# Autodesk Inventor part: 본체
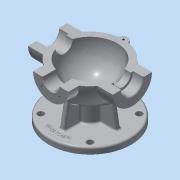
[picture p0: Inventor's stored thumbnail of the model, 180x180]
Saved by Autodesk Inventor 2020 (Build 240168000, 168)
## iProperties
Created: 2015-12
Part Number: 본체
Material: 알루미늄 6061
Document SubType Name: Modeling
Designer: mduedu
Density: 2.71 g/cm^3
Mass: 966.367 g
Surface Area: 788.536 cm^2
Volume: 356.593 cm^3
Appearance: 알루미늄 - 평지
Author: mduedu
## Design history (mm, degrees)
sketch "스케치1"
  geometry: L1 (-53, 0)-(53, 0); A1 r 53 centre (0, 0) between (53, 0) and (-53, 0); 2 further points
  constraints: 2 coincident, 2 end point, 2 point on circle, 1 centre point, 1 horizontal, 1 midpoint
  dimensions: "d0" = 53 radius of A1
revolve "회전1" sketch "스케치1" stored, may be unused: angle "d2" = 90 deg
feature "쉘1" dims "d11" = 10
node "작업 평면1"
sketch "스케치2"
  geometry: C1 r 31 at (0, 0); 1 further point
  constraints: 1 centre point, 1 coincident
  dimensions: "d4" = 62 diameter of C1
extrude "돌출1" join sketch "스케치2" stored distance "d5" = 10; taper "d6" = 0 deg
node "작업 평면2"
sketch "스케치3"
  geometry: C1 r 28 at (0, 0); 1 further point
  constraints: 1 centre point, 1 coincident
  dimensions: "d8" = 56 diameter of C1
extrude "돌출2" join sketch "스케치3" stored distance "d9" = 10; taper "d10" = 0 deg
hole "구멍1" diameter "d14" = 35; stored, may be unused: countersink angle "d18" = 90 deg, drill point angle "d20" = 0 deg; dims "d12" = 10, "d13" = 10, "d15" = 6, "d16" = 4, "d17" = 2, "d19" = 16
hole "구멍2" diameter "d23" = 27; stored, may be unused: countersink angle "d27" = 90 deg, drill point angle "d29" = 0 deg; dims "d21" = 10, "d22" = 10, "d24" = 6, "d25" = 4, "d26" = 2, "d28" = 16
fillet "모깎기1" dims "d30" = 0.3
hole "구멍3" diameter "d33" = 26; stored, may be unused: countersink angle "d37" = 90 deg, drill point angle "d39" = 0 deg; dims "d31" = 10, "d32" = 10, "d34" = 6, "d35" = 4, "d36" = 2, "d38" = 16
chamfer "모따기1" distance "d40" = 1; stored, may be unused: second distance "d41" = 2, angle "d42" = 45 deg
sketch "스케치4"
  geometry: L1 (0, 0)-(0, -25); L2 (0, 0)-(-17.678, -17.678); A1 r 25 centre (0, 0) between (-17.678, -17.678) and (0, -25); 1 further point
  constraints: 4 end point, 2 point on circle, 1 centre point, 1 coincident, 1 vertical
  dimensions: "d43" = 50 diameter of A1; "d47" = 45 deg angle of L1 L2
hole "구멍4" sketch "스케치4" at (-17.678, -17.678) diameter "d49" = 3.242; stored, may be unused: countersink angle "d53" = 90 deg, drill point angle "d55" = 118 deg; dims "d50" = 11, "d51" = 4, "d52" = 2, "d54" = 13
sketch "스케치5"
  geometry: L1 (0, 0)-(0, -20); L2 (0, 0)-(-14.142, -14.142); A1 r 20 centre (0, 0) between (0, -20) and (-14.142, -14.142); 2 further points
  constraints: 4 end point, 2 coincident, 2 point on circle, 1 centre point, 1 vertical
  dimensions: "d59" = 40 diameter of A1; "d65" = 45 deg angle of L1 L2
hole "구멍5" sketch "스케치5" at (-14.142, -14.142) diameter "d67" = 3.242; stored, may be unused: countersink angle "d71" = 90 deg, drill point angle "d73" = 118 deg; dims "d68" = 8, "d69" = 4, "d70" = 2, "d72" = 10
node "작업 평면3"
sketch "스케치6"
  geometry: C1 r 65 at (0, 0); 1 further point
  constraints: 1 centre point, 1 coincident
  dimensions: "d78" = 130 diameter of C1
extrude "돌출3" join sketch "스케치6" distance "d80" = 10; taper "d81" = 0 deg
sketch "스케치7"
  geometry: C1 r 20 at (0, 0); 1 further point
  constraints: 1 centre point, 1 coincident
  dimensions: "d82" = 40 diameter of C1
extrude "돌출4" join sketch "스케치7" stored distance "d84" = 10; taper "d85" = 0 deg
sketch "스케치8"
  geometry: 2 further points
  constraints: 1 coincident
hole "구멍6" sketch "스케치8" at (0, 0) diameter "d86" = 20; stored, may be unused: countersink angle "d90" = 90 deg, drill point angle "d92" = 118 deg; dims "d87" = 7, "d88" = 40, "d89" = 5, "d91" = 10
fillet "모깎기2" dims "d93" = 0.3
sketch "스케치9"
  geometry: L1 (65, -75)-(-65, -75) reference; L2 (-45, -75)-(-38.245, -36.692); A1 r 53 centre (0, 0) between (42.988, 31) and (42.988, -31) reference; 1 further point
  constraints: 2 end point, 1 point on circle, 1 point on line
  dimensions: "d94" = 45 horizontal distance of L2.start point (0, 0); "d95" = 80 deg angle of L2 L1
feature "리브1" sketch "스케치9" dims "d96" = 1, "d97" = 8, "d98" = 0, "d99" = 0, "d100" = 1, "d101" = 1
sketch "스케치10"
  geometry: L1 (0, 0)-(0, -55); L2 (0, 0)-(-38.891, -38.891); A1 r 55 centre (0, 0) between (0, -55) and (-38.891, -38.891); 2 further points
  constraints: 4 end point, 2 coincident, 2 point on circle, 1 centre point, 1 vertical
  dimensions: "d105" = 110 diameter of A1; "d107" = 45 deg angle of L1 L2
hole "구멍7" sketch "스케치10" at (-38.891, -38.891) diameter "d109" = 10; stored, may be unused: countersink angle "d113" = 90 deg, drill point angle "d115" = 118 deg; dims "d110" = 7, "d111" = 40, "d112" = 5, "d114" = 10
fillet "모깎기3" dims "d120" = 3
fillet "모깎기4" dims "d121" = 3, "d122" = 3
fillet "모깎기5" dims "d123" = 3
fillet "모깎기6" dims "d124" = 3
sketch "스케치11"
  geometry: C1 r 5 at (-38.891, 38.891) reference; C2 r 5 at (38.891, 38.891) reference; C3 r 5 at (38.891, -38.891) reference; C4 r 5 at (-38.891, -38.891) reference; C5 r 20 at (0, 0) reference; C6 r 65 at (0, 0) reference; 1 further point
  constraints: 3 other
feature "엠보싱1" sketch "스케치11" dims "d0" = 53, "d125" = 0.5, "d126" = 0
sketch "스케치12"
  geometry: L1 (0, 100)-(0, -100); L2 (0, 100)-(100, 100); L3 (100, 100)-(100, -100); L4 (100, -100)-(0, -100); 2 further points
  constraints: 8 end point, 3 perpendicular, 1 coincident, 1 midpoint, 1 vertical
  dimensions: "d127" = 200 distance of L2.end L3.end; "d129" = 100 distance between parallel lines of L1 L3
extrude "돌출5" cut sketch "스케치12" extent not by distance; stored distance "d130" = 10; taper "d131" = 0 deg
sketch "스케치13"
  geometry: C1 r 7 at (0, 53); A1 r 53 centre (0, 0) between (42.113, 32.179) and (-42.113, 32.179) reference; 1 further point
  constraints: 1 centre point, 1 point on circle
  dimensions: "d132" = 14 diameter of C1
extrude "돌출6" join sketch "스케치13" distance "d134" = 15; taper "d135" = 0 deg
hole "구멍8" diameter "d139" = 3.242; stored, may be unused: countersink angle "d143" = 90 deg, drill point angle "d145" = 118 deg; dims "d140" = 8, "d141" = 4, "d142" = 2, "d144" = 10, "d148" = 10, "d149" = 10
fillet "모깎기7" dims "d146" = 3
fillet "모깎기8" dims "d147" = 3
node "솔리드1"
mirror "대칭1"
mirror "대칭2"
pattern_circular "원형 패턴1" dims angle "d57" = 360 deg
mirror "대칭3"
pattern_circular "원형 패턴2" dims angle "d75" = 360 deg
pattern_circular "원형 패턴3" dims angle "d103" = 360 deg
pattern_circular "원형 패턴4" dims angle "d118" = 360 deg
node "투영된 루프1"
other parameters: "d3" = 67, "d7" = 62, "d77" = -85
